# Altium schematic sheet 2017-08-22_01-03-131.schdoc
size 370 x 127 mm; SheetNumber: 1; SheetTotal: 1
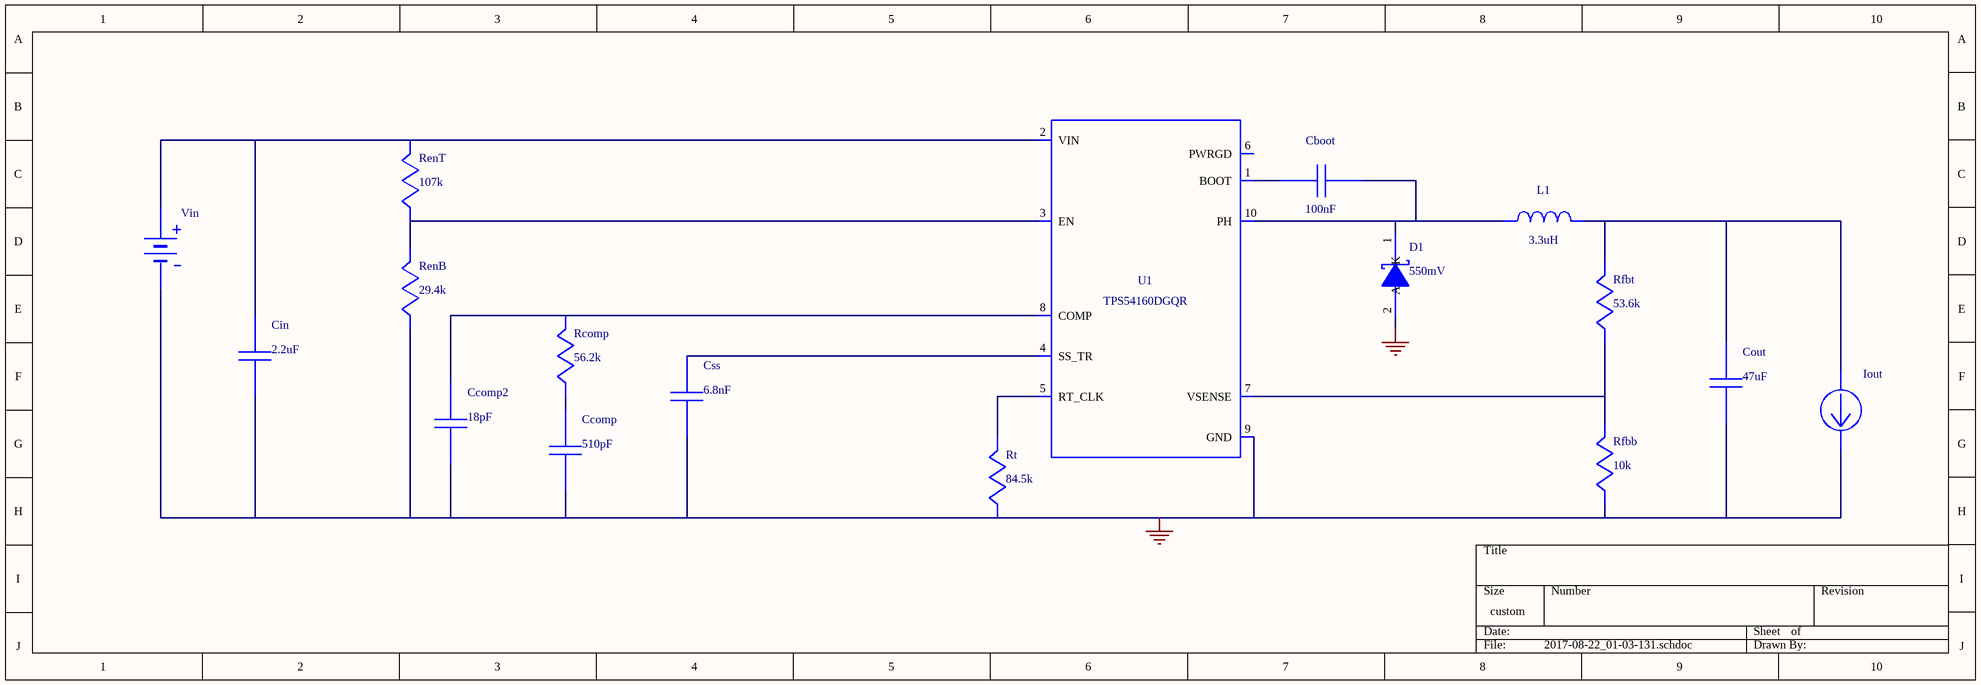
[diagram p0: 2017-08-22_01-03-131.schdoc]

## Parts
Cboot  value 100nF  (hidden comment: GRM155R61A104KA01D)
Ccomp  value 510pF  (hidden comment: CL21C511JBANNNC)
Ccomp2  value 18pF  (hidden comment: C0805C180K5GACTU)
Cin  value 2.2uF  (hidden comment: GRM188R61A225KE34D)
Cout  value 47uF  (hidden comment: C2012X5R1A476M125AC)
Css  value 6.8nF  (hidden comment: CC0805KRX7R9BB682)
D1  value 550mV  (hidden comment: SS24FL)
Iout  WB_CURRENT_LOAD  (value not drawn)
L1  value 3.3uH  (hidden comment: SRN6045-3R3Y)
Rcomp  value 56.2k  (hidden comment: CRCW040256K2FKED)
RenB  value 29.4k  (hidden comment: CRCW040229K4FKED)
RenT  value 107k  (hidden comment: CRCW0402107KFKED)
Rfbb  value 10k  (hidden comment: CRCW040210K0FKED)
Rfbt  value 53.6k  (hidden comment: CRCW040253K6FKED)
Rt  value 84.5k  (hidden comment: CRCW040284K5FKED)
U1  TPS54140DGQR  (value not drawn)
Vin  WB_BATTERY  (value not drawn)

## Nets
0: Ccomp.2 Ccomp2.2 Cin.2 Cout.2 Css.2 D1.2(A) Iout.2(-) RenB.2 Rfbb.2 Rt.2 U1.9(GND) U1.11(EPAD) Vin.2(-)
NetCboot_1: Cboot.1 U1.1(BOOT)
NetCboot_2: Cboot.2 D1.1(K) L1.2 U1.10(PH)
NetCcomp2_1: Ccomp2.1 Rcomp.1 U1.8(COMP)
NetCcomp_1: Ccomp.1 Rcomp.2
NetCin_1: Cin.1 RenT.1 U1.2(VIN) Vin.1(+)
NetCout_1: Cout.1 Iout.1(+) L1.1 Rfbt.1
NetCss_1: Css.1 U1.4(SS_TR)
NetRenB_1: RenB.1 RenT.2 U1.3(EN)
NetRfbb_1: Rfbb.1 Rfbt.2 U1.7(VSENSE)
NetRt_1: Rt.1 U1.5(RT_CLK)

Not connected (* = marked no-connect by the designer): U1 6(PWRGD)

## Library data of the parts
Cboot = GRM155R61A104KA01D: GRM155R61A104KA0; Manufacturer Name: MuRata
Ccomp = CL21C511JBANNNC: Manufacturer Name: Samsung Electro-Mechanics
Ccomp2 = C0805C180K5GACTU: Manufacturer Name: Kemet
Cin = GRM188R61A225KE34D: GRM188R61A225KE3; Manufacturer Name: MuRata
Cout = C2012X5R1A476M125AC: C2012X5R1A476M12; Manufacturer Name: TDK
Css = CC0805KRX7R9BB682: CC0805KRX7R9BB68; Manufacturer Name: Yageo America
D1 = SS24FL: Manufacturer Name: Fairchild Semiconductor
L1 = SRN6045-3R3Y: Manufacturer Name: Bourns
Rcomp = CRCW040256K2FKED: Manufacturer Name: Vishay-Dale
RenB = CRCW040229K4FKED: Manufacturer Name: Vishay-Dale
RenT = CRCW0402107KFKED: Manufacturer Name: Vishay-Dale
Rfbb = CRCW040210K0FKED: Manufacturer Name: Vishay-Dale
Rfbt = CRCW040253K6FKED: Manufacturer Name: Vishay-Dale
Rt = CRCW040284K5FKED: Manufacturer Name: Vishay-Dale
U1 = TPS54140DGQR: TPS54160DGQR; Manufacturer Name: Texas Instruments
